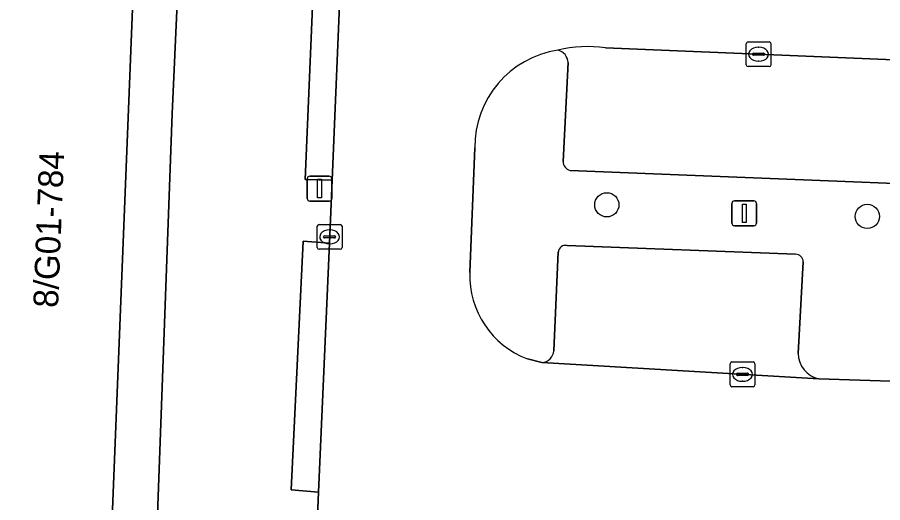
# Model space of a CAD drawing. Extents: x 160786 to 161429, y 386828 to 387485.
# Drawn here: x 160856.14 to 160891.04, y 387369.39 to 387388.98 of the extents above; entities that cross this region are included whole.
import ezdxf

# ---------------------------------------------------------------- set-up
doc = ezdxf.new("R2010")
doc.units = 0
for name, color, linetype in [('IMGEO_Boom', 7, 'Continuous'), ('IMGEO_Erf', 7, 'Continuous'), ('IMGEO_Groenvoorziening', 7, 'Continuous'), ('IMGEO_Kolk', 7, 'Continuous'), ('IMGEO_Lichtmast', 7, 'Continuous'), ('IMGEO_Pand', 7, 'Continuous'), ('IMGEO_Pand_nummerreeks', 7, 'Continuous'), ('IMGEO_Pand_overbouw', 7, 'Continuous'), ('IMGEO_Parkeervlak_open', 7, 'Continuous'), ('IMGEO_Rijbaan_lokaal_open', 7, 'Continuous'), ('IMGEO_Voetpad_open', 7, 'Continuous')]:
    doc.layers.add(name, color=color, linetype=linetype)

msp = doc.modelspace()

# ---------------------------------------------------------------- linework, layer by layer
at = {"layer": 'IMGEO_Boom'}
for centre in [(160879.917, 387381.414), (160890.422, 387380.945)]:
    msp.add_circle(centre, 0.489, dxfattribs=at)
at = {"layer": 'IMGEO_Erf'}
msp.add_lwpolyline([(160860.677, 387338.395), (160862.385, 387385.082), (160864.207, 387425.291), (160862.224, 387425.37), (160858.759, 387338.472)], close=True, dxfattribs=at)
at = {"layer": 'IMGEO_Groenvoorziening'}
for points in [[(160878.152, 387383.168), (160878.353, 387387.157)], [(160874.591, 387383.712), (160874.392, 387378.678)], [(160902.63, 387381.834), (160878.436, 387382.804)], [(160877.776, 387375.527), (160877.962, 387379.511)], [(160878.313, 387379.769), (160887.532, 387379.417)], [(160887.842, 387379.119), (160887.637, 387375.417)], [(160876.713, 387375.193), (160877.299, 387375.049)], [(160888.467, 387374.389), (160891.772, 387374.279)]]:
    msp.add_lwpolyline(points, dxfattribs=at)
for centre, radius, start, end in [((160878.54, 387383.751), 3.949, 98.6746, 180.5719), ((160877.828, 387387.143), 0.525, 1.5379, 77.2536), ((160878.531, 387383.171), 0.379, 180.4405, 255.4836), ((160878.242, 387379.498), 0.28, 75.2246, 177.4103), ((160887.531, 387379.106), 0.311, 2.4005, 89.8609), ((160878.006, 387378.57), 3.616, 178.2846, 249.0424), ((160877.271, 387375.554), 0.506, 273.2263, 356.8937), ((160888.699, 387375.426), 1.062, 180.4696, 257.3647)]:
    msp.add_arc(centre, radius, start, end, dxfattribs=at)
at = {"layer": 'IMGEO_Kolk'}
for p, q in [((160885.538, 387387.066), (160885.538, 387387.918)), ((160885.613, 387387.992), (160886.465, 387387.992)), ((160886.539, 387387.918), (160886.539, 387387.066)), ((160885.797, 387387.486), (160885.797, 387387.498)), ((160885.84, 387387.535), (160886.238, 387387.535)), ((160886.026, 387387.772), (160886.051, 387387.772)), ((160886.281, 387387.498), (160886.281, 387387.486)), ((160886.235, 387387.449), (160885.837, 387387.449)), ((160886.049, 387387.212), (160886.024, 387387.212)), ((160886.465, 387386.992), (160885.613, 387386.992)), ((160868.237, 387379.695), (160868.237, 387380.547)), ((160868.312, 387380.621), (160869.164, 387380.621)), ((160869.238, 387380.547), (160869.238, 387379.695)), ((160868.496, 387380.115), (160868.496, 387380.127)), ((160868.539, 387380.164), (160868.937, 387380.164)), ((160868.725, 387380.401), (160868.75, 387380.401)), ((160868.98, 387380.127), (160868.98, 387380.115)), ((160868.934, 387380.078), (160868.536, 387380.078)), ((160868.748, 387379.841), (160868.723, 387379.841)), ((160869.164, 387379.621), (160868.312, 387379.621)), ((160884.89, 387374.145), (160884.89, 387374.997)), ((160884.965, 387375.071), (160885.817, 387375.071)), ((160885.891, 387374.997), (160885.891, 387374.145)), ((160885.149, 387374.565), (160885.149, 387374.577)), ((160885.192, 387374.614), (160885.59, 387374.614)), ((160885.378, 387374.851), (160885.403, 387374.851)), ((160885.633, 387374.577), (160885.633, 387374.565)), ((160885.587, 387374.528), (160885.189, 387374.528)), ((160885.401, 387374.291), (160885.376, 387374.291)), ((160885.817, 387374.071), (160884.965, 387374.071))]:
    msp.add_line(p, q, dxfattribs=at)
for points in [[(160885.538, 387387.066), (160885.538, 387387.918)], [(160885.613, 387387.992), (160886.465, 387387.992)], [(160886.539, 387387.918), (160886.539, 387387.066)], [(160886.465, 387386.992), (160885.613, 387386.992)], [(160868.237, 387379.695), (160868.237, 387380.547)], [(160868.312, 387380.621), (160869.164, 387380.621)], [(160869.238, 387380.547), (160869.238, 387379.695)], [(160869.164, 387379.621), (160868.312, 387379.621)], [(160884.89, 387374.145), (160884.89, 387374.997)], [(160884.965, 387375.071), (160885.817, 387375.071)], [(160885.891, 387374.997), (160885.891, 387374.145)], [(160885.817, 387374.071), (160884.965, 387374.071)]]:
    msp.add_lwpolyline(points, dxfattribs=at)
for centre, radius, start, end in [((160885.615, 387387.916), 0.0765, 91.552, 178.448), ((160885.615, 387387.916), 0.0765, 91.552, 178.448), ((160886.463, 387387.916), 0.0765, 1.552, 88.448), ((160886.463, 387387.916), 0.0765, 1.552, 88.448), ((160885.837, 387387.495), 0.0403, 85.8775, 175.7526), ((160885.834, 387387.485), 0.0366, 178.938, 274.7102), ((160886.238, 387387.492), 0.043, 264.8664, 352.4533), ((160886.242, 387387.497), 0.0386, 1.7309, 96.639), ((160885.615, 387387.068), 0.0765, 181.552, 268.448), ((160885.615, 387387.068), 0.0765, 181.552, 268.448), ((160886.463, 387387.068), 0.0765, 271.552, 358.448), ((160886.463, 387387.068), 0.0765, 271.552, 358.448), ((160868.314, 387380.545), 0.0765, 91.552, 178.448), ((160868.314, 387380.545), 0.0765, 91.552, 178.448), ((160869.162, 387380.545), 0.0765, 1.552, 88.448), ((160869.162, 387380.545), 0.0765, 1.552, 88.448), ((160868.536, 387380.124), 0.0403, 85.8775, 175.7526), ((160868.941, 387380.126), 0.0386, 1.7309, 96.639), ((160868.533, 387380.114), 0.0366, 178.938, 274.7102), ((160868.937, 387380.121), 0.043, 264.8664, 352.4533), ((160868.314, 387379.697), 0.0765, 181.552, 268.448), ((160868.314, 387379.697), 0.0765, 181.552, 268.448), ((160869.162, 387379.697), 0.0765, 271.552, 358.448), ((160869.162, 387379.697), 0.0765, 271.552, 358.448), ((160884.967, 387374.995), 0.0765, 91.552, 178.448), ((160884.967, 387374.995), 0.0765, 91.552, 178.448), ((160885.815, 387374.995), 0.0765, 1.552, 88.448), ((160885.815, 387374.995), 0.0765, 1.552, 88.448), ((160885.189, 387374.574), 0.0403, 85.8775, 175.7526), ((160885.186, 387374.564), 0.0366, 178.938, 274.7102), ((160885.59, 387374.571), 0.043, 264.8664, 352.4533), ((160885.594, 387374.576), 0.0386, 1.7309, 96.639), ((160884.967, 387374.147), 0.0765, 181.552, 268.448), ((160884.967, 387374.147), 0.0765, 181.552, 268.448), ((160885.815, 387374.147), 0.0765, 271.552, 358.448), ((160885.815, 387374.147), 0.0765, 271.552, 358.448)]:
    msp.add_arc(centre, radius, start, end, dxfattribs=at)
for centre, major_axis, ratio, start_param, end_param in [((160886.025, 387387.492), (-0.387, 0.002), 0.722429, 4.712389, 7.853982), ((160886.05, 387387.492), (-0.39, 0.002), 0.717154, 1.570796, 4.712389), ((160868.724, 387380.121), (-0.387, 0.002), 0.722429, 4.712389, 7.853982), ((160868.749, 387380.121), (-0.39, 0.002), 0.717154, 1.570796, 4.712389), ((160885.377, 387374.571), (-0.387, 0.002), 0.722429, 4.712389, 7.853982), ((160885.402, 387374.571), (-0.39, 0.002), 0.717154, 1.570796, 4.712389)]:
    msp.add_ellipse(centre, major_axis=major_axis, ratio=ratio, start_param=start_param, end_param=end_param, dxfattribs=at)
at = {"layer": 'IMGEO_Lichtmast'}
for p, q in [((160867.835, 387381.668), (160867.835, 387382.468)), ((160867.835, 387382.468), (160867.835, 387381.668)), ((160867.935, 387382.568), (160868.725, 387382.568)), ((160868.725, 387382.568), (160867.935, 387382.568)), ((160868.825, 387382.468), (160868.825, 387381.668)), ((160868.825, 387381.668), (160868.825, 387382.468)), ((160868.725, 387381.568), (160867.935, 387381.568)), ((160867.935, 387381.568), (160868.725, 387381.568)), ((160885.063, 387381.571), (160885.853, 387381.571)), ((160885.853, 387381.571), (160885.063, 387381.571)), ((160884.963, 387380.671), (160884.963, 387381.471)), ((160884.963, 387381.471), (160884.963, 387380.671)), ((160885.953, 387381.471), (160885.953, 387380.671)), ((160885.953, 387380.671), (160885.953, 387381.471)), ((160885.853, 387380.571), (160885.063, 387380.571)), ((160885.063, 387380.571), (160885.853, 387380.571))]:
    msp.add_line(p, q, dxfattribs=at)
for points in [[(160868.255, 387382.443), (160868.405, 387382.443), (160868.405, 387381.693), (160868.255, 387381.693), (160868.255, 387382.443)], [(160885.383, 387381.446), (160885.533, 387381.446), (160885.533, 387380.696), (160885.383, 387380.696), (160885.383, 387381.446)]]:
    msp.add_lwpolyline(points, dxfattribs=at)
for centre, start, end in [((160867.935, 387382.468), 90, 180), ((160867.935, 387382.468), 90, 180), ((160868.725, 387382.468), 0, 90), ((160868.725, 387382.468), 360, 90), ((160867.935, 387381.668), 180, 270), ((160867.935, 387381.668), 180, 270), ((160868.725, 387381.668), 270, 0), ((160868.725, 387381.668), 270, 0), ((160885.063, 387381.471), 90, 180), ((160885.063, 387381.471), 90, 180), ((160885.853, 387381.471), 0, 90), ((160885.853, 387381.471), 360, 90), ((160885.063, 387380.671), 180, 270), ((160885.063, 387380.671), 180, 270), ((160885.853, 387380.671), 270, 0), ((160885.853, 387380.671), 270, 0)]:
    msp.add_arc(centre, 0.1, start, end, dxfattribs=at)
at = {"layer": 'IMGEO_Pand'}
msp.add_lwpolyline([(160858.759, 387338.472), (160862.224, 387425.37), (160864.207, 387425.291), (160864.215, 387425.491), (160864.358, 387429.081), (160864.446, 387431.292), (160864.467, 387431.808), (160860.639, 387431.961), (160856.522, 387432.125), (160856.267, 387425.726), (160851.747, 387425.906), (160848.277, 387338.878), (160855.929, 387338.573), (160854.813, 387310.588), (160849.421, 387310.803), (160849.286, 387307.423), (160866.131, 387306.751), (160867.143, 387306.711), (160867.946, 387326.856), (160868.138, 387331.665), (160866.613, 387331.726), (160866.869, 387338.148), (160860.677, 387338.395)], close=True, dxfattribs=at)
at = {"layer": 'IMGEO_Pand_overbouw'}
msp.add_lwpolyline([(160860.677, 387338.395), (160862.385, 387385.082), (160864.207, 387425.291), (160862.224, 387425.37), (160858.759, 387338.472)], close=True, dxfattribs=at)
at = {"layer": 'IMGEO_Parkeervlak_open'}
for points in [[(160904.1, 387386.742), (160879.861, 387387.749)], [(160878.353, 387387.157), (160878.152, 387383.168)], [(160878.436, 387382.804), (160902.63, 387381.834)], [(160877.962, 387379.511), (160877.776, 387375.527)], [(160887.532, 387379.417), (160878.313, 387379.769)], [(160887.637, 387375.417), (160887.842, 387379.119)], [(160877.299, 387375.049), (160888.467, 387374.389)]]:
    msp.add_lwpolyline(points, dxfattribs=at)
for centre, radius, start, end in [((160879.142, 387382.809), 4.992, 81.7239, 103.8906), ((160877.828, 387387.143), 0.525, 1.5379, 77.2536), ((160878.531, 387383.171), 0.379, 180.4405, 255.4836), ((160878.242, 387379.498), 0.28, 75.2246, 177.4103), ((160887.531, 387379.106), 0.311, 2.4005, 89.8609), ((160877.271, 387375.554), 0.506, 273.2263, 356.8937), ((160888.699, 387375.426), 1.062, 180.4696, 257.3647)]:
    msp.add_arc(centre, radius, start, end, dxfattribs=at)
at = {"layer": 'IMGEO_Rijbaan_lokaal_open'}
for points in [[(160869.895, 387408.453), (160869.865, 387407.3), (160869.755, 387404.296), (160868.835, 387382.412), (160868.727, 387379.861), (160868.295, 387369.815), (160867.729, 387355.931)], [(160879.861, 387387.749), (160904.1, 387386.742), (160907.453, 387386.639), (160915.576, 387386.275), (160917.798, 387386.088)], [(160874.392, 387378.678), (160874.591, 387383.712)], [(160916.607, 387373.28), (160891.772, 387374.279), (160888.467, 387374.389), (160877.299, 387375.049), (160876.713, 387375.193)]]:
    msp.add_lwpolyline(points, dxfattribs=at)
for centre, radius, start, end in [((160878.54, 387383.751), 3.949, 98.6746, 180.5719), ((160879.142, 387382.809), 4.992, 81.7239, 103.8906), ((160878.006, 387378.57), 3.616, 178.2846, 249.0424)]:
    msp.add_arc(centre, radius, start, end, dxfattribs=at)
at = {"layer": 'IMGEO_Voetpad_open'}
for points in [[(160954.685, 387431.126), (160876.143, 387434.371), (160856.696, 387435.174), (160853.526, 387434.643), (160853.431, 387432.318), (160851.982, 387432.381), (160851.747, 387425.906), (160856.267, 387425.726), (160856.522, 387432.125), (160860.639, 387431.961), (160864.467, 387431.808), (160864.446, 387431.292), (160864.358, 387429.081), (160864.215, 387425.491), (160864.207, 387425.291), (160862.385, 387385.082), (160860.677, 387338.395)], [(160867.729, 387355.931), (160868.295, 387369.815), (160867.185, 387369.911), (160867.666, 387379.947), (160868.727, 387379.861), (160868.835, 387382.412), (160867.747, 387382.44), (160868.679, 387404.348), (160869.755, 387404.296), (160869.865, 387407.3), (160868.759, 387407.315), (160868.814, 387408.689)]]:
    msp.add_lwpolyline(points, dxfattribs=at)
for points in [[(160868.835, 387382.412), (160869.755, 387404.296), (160868.679, 387404.348), (160867.747, 387382.44)], [(160868.727, 387379.861), (160867.666, 387379.947), (160867.185, 387369.911), (160868.295, 387369.815)]]:
    msp.add_lwpolyline(points, close=True, dxfattribs=at)

# ---------------------------------------------------------------- texts
at = {"layer": 'IMGEO_Pand_nummerreeks'}
msp.add_text('8/G01-784', height=1, rotation=87.7166, dxfattribs=at).set_placement((160857.783, 387377.246))

doc.saveas('drawing.dxf')
